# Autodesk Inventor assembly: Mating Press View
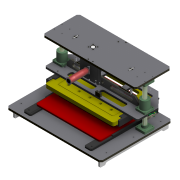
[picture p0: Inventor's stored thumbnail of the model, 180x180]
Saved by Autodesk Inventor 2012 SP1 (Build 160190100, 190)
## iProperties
Shininess: 0.0
Created: 2000-06
Part Number: Mating Press View
Description: PRESS,  BONDING FIXTURE - BASE AND DISPLAY CASE
Document SubType Name: Assembly
Designer: Ron
Density: 0.0
Volumn: 0.0
Area: 0.0
PropertySet Name: Model Information
Control State: 0
Master: False
Checked Out: False
Author: Ron
Revision Number: 03
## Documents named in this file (12)
- D:\AOTC\Autodesk Inventor 2012 Essential for New Users\Autodesk Inventor 2012 Essentials - Project Files\Learning\Workspace\Mating Press View.iam
- D:\AOTC\Autodesk Inventor 2012 Essential for New Users\Autodesk Inventor 2012 Essentials - Project Files\Learning\Workspace\Parts\Assemble_Plate_Bottom.ipt
- D:\AOTC\Autodesk Inventor 2012 Essential for New Users\Autodesk Inventor 2012 Essentials - Project Files\Learning\Workspace\Sub-Assemblies\Base_Plate.iam
- D:\AOTC\Autodesk Inventor 2012 Essential for New Users\Autodesk Inventor 2012 Essentials - Project Files\Learning\Workspace\Sub-Assemblies\Press_Cam.iam
- D:\AOTC\Autodesk Inventor 2012 Essential for New Users\Autodesk Inventor 2012 Essentials - Project Files\Learning\Workspace\Sub-Assemblies\Top_Plate.iam
- D:\AOTC\Autodesk Inventor 2012 Essential for New Users\Autodesk Inventor 2012 Essentials - Project Files\Learning\Workspace\Parts\SHAFT.ipt
- D:\AOTC\Autodesk Inventor 2012 Essential for New Users\Autodesk Inventor 2012 Essentials - Project Files\Learning\Workspace\Parts\ACE-6501.ipt
- D:\AOTC\Autodesk Inventor 2012 Essential for New Users\Autodesk Inventor 2012 Essentials - Project Files\Learning\Workspace\Parts\SHOCK MOUNT.ipt
- D:\AOTC\Autodesk Inventor 2012 Essential for New Users\Autodesk Inventor 2012 Essentials - Project Files\Learning\Workspace\Sub-Assemblies\detent-01.iam
- D:\AOTC\Autodesk Inventor 2012 Essential for New Users\Autodesk Inventor 2012 Essentials - Project Files\Learning\Workspace\Parts\Top_Component.ipt
- C:\Documents and Settings\All Users\Autodesk Learning\Inventor 11\Introduction to 3D Design\Components\detent.iam
- D:\AOTC\Autodesk Inventor 2012 Essential for New Users\Autodesk Inventor 2012 Essentials - Project Files\Learning\Workspace\Sub-Assemblies\Press Clamp Assembly 2.iam
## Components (12 placed, 10 different names)
1. Base_Plate:1 [sub-assembly] — Insert:1, Insert:2, Angle:2, Mate:13, Mate:14, Angle:5, Mate:15, Flush:2, Mate:16
2. Top_Plate:1 [sub-assembly] — Insert:3, Angle:2, Mate:10, Mate:11, Insert:5, Angle:3, Flush:1, Angle:6
3. Press Clamp Assembly 2:1 [sub-assembly] — Mate:21, Angle:6, Mate:22, Mate:23, Tangent:2
4. Press_Cam:2 [sub-assembly] — Mate:10, Mate:11
5. SHAFT:1 — Insert:1, Mate:21
6. SHAFT:2 — Insert:2, Insert:3
7. Adjustable_Stop:1 — Mate:9, Flush:1
8. SHOCK MOUNT:1 — Mate:9, Insert:5, Angle:3
9. detent-01:1 [sub-assembly] — Mate:13, Mate:14, Angle:5, Flush:3, Flush:4, Mate:20
10. detent-01:2 [sub-assembly] — Mate:16, Flush:3, Flush:4, Mate:19
11. Assemble_Plate_Bottom:1 — Mate:15, Flush:2, Mate:19, Mate:20
12. Top_Component:1 — Mate:22, Mate:23, Tangent:2
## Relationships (25: Mate 12, Insert 4, Angle 4, Flush 4, Tangent 1)
- Mate:9: Adjustable_Stop:1 ↔ SHOCK MOUNT:1
- Insert:1: Base_Plate:1 ↔ SHAFT:1
- Insert:2: Base_Plate:1 ↔ SHAFT:2
- Insert:3: Top_Plate:1 ↔ SHAFT:2
- Angle:2: Base_Plate:1 ↔ Top_Plate:1
- Mate:10: Top_Plate:1 ↔ Press_Cam:2
- Mate:11: Top_Plate:1 ↔ Press_Cam:2
- Insert:5: Top_Plate:1 ↔ SHOCK MOUNT:1
- Angle:3: Top_Plate:1 ↔ SHOCK MOUNT:1
- Flush:1: Top_Plate:1 ↔ Adjustable_Stop:1
- Mate:13: Base_Plate:1 ↔ detent-01:1
- Mate:14: Base_Plate:1 ↔ detent-01:1
- Angle:5: Base_Plate:1 ↔ detent-01:1
- Mate:15: Base_Plate:1 ↔ Assemble_Plate_Bottom:1
- Flush:2: Base_Plate:1 ↔ Assemble_Plate_Bottom:1
- Mate:16: Base_Plate:1 ↔ detent-01:2
- Flush:3: detent-01:1 ↔ detent-01:2
- Flush:4: detent-01:1 ↔ detent-01:2
- Mate:19: detent-01:2 ↔ Assemble_Plate_Bottom:1
- Mate:20: detent-01:1 ↔ Assemble_Plate_Bottom:1
- Mate:21: Press Clamp Assembly 2:1 ↔ SHAFT:1
- Angle:6: Top_Plate:1 ↔ Press Clamp Assembly 2:1
- Mate:22: Press Clamp Assembly 2:1 ↔ Top_Component:1
- Mate:23: Press Clamp Assembly 2:1 ↔ Top_Component:1
- Tangent:2: Press Clamp Assembly 2:1 ↔ Top_Component:1
